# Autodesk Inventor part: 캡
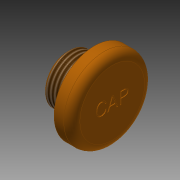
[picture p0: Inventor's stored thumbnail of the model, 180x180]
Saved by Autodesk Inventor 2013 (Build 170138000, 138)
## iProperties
Created: 2017-06
Part Number: 캡
Material: ABS 플라스틱
Document SubType Name: Modeling
Designer: mduedu
Density: 1 g/cm^3
Author: mduedu
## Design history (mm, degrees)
sketch "스케치1"
  geometry: L1 (0, 0)-(11, 0); L2 (11, 0)-(11, 10); L3 (11, 10)-(6.5, 10); L4 (0, 6)-(0, 0); L5 (0, 6)-(6, 6); L6 (6, 6)-(6, 9); L7 (6, 9)-(6.5, 9); L8 (6.5, 9)-(6.5, 10)
  constraints: 16 end point, 2 horizontal, 2 parallel, 2 perpendicular, 2 point on line, 1 vertical
  dimensions: "d0" = 20 diameter of L3 L1; "d2" = 12 diameter of L5 L1; "d6" = 5 distance between parallel lines of L2 L6; "d7" = 0.5 distance between parallel lines of L8 L6; "d8" = 18 diameter of L7 L1; "d9" = 6 distance between parallel lines of L6 L4
revolve "회전1" sketch "스케치1" stored, may be unused: angle "d10" = 90 deg
hole "구멍1" diameter "d22" = 8; stored, may be unused: countersink angle "d26" = 90 deg, drill point angle "d28" = 0 deg; dims "d23" = 6, "d24" = 4, "d25" = 2, "d27" = 5, "d32" = 10, "d33" = 10
chamfer "모따기1" distance "d13" = 0.5; stored, may be unused: second distance "d14" = 2, angle "d15" = 45 deg
fillet "모깎기3" dims "d29" = 1
fillet "모깎기1" dims "d16" = 0.1
fillet "모깎기2" dims "d17" = 2
sketch "스케치3"
  geometry: 2 further points
  constraints: 1 coincident, 1 other
feature "엠보싱1" sketch "스케치3" dims "d16" = 0.1, "d18" = 0.2, "d19" = 0
feature "스레드1" dims "d30" = 10, "d31" = 0
node "솔리드1"
